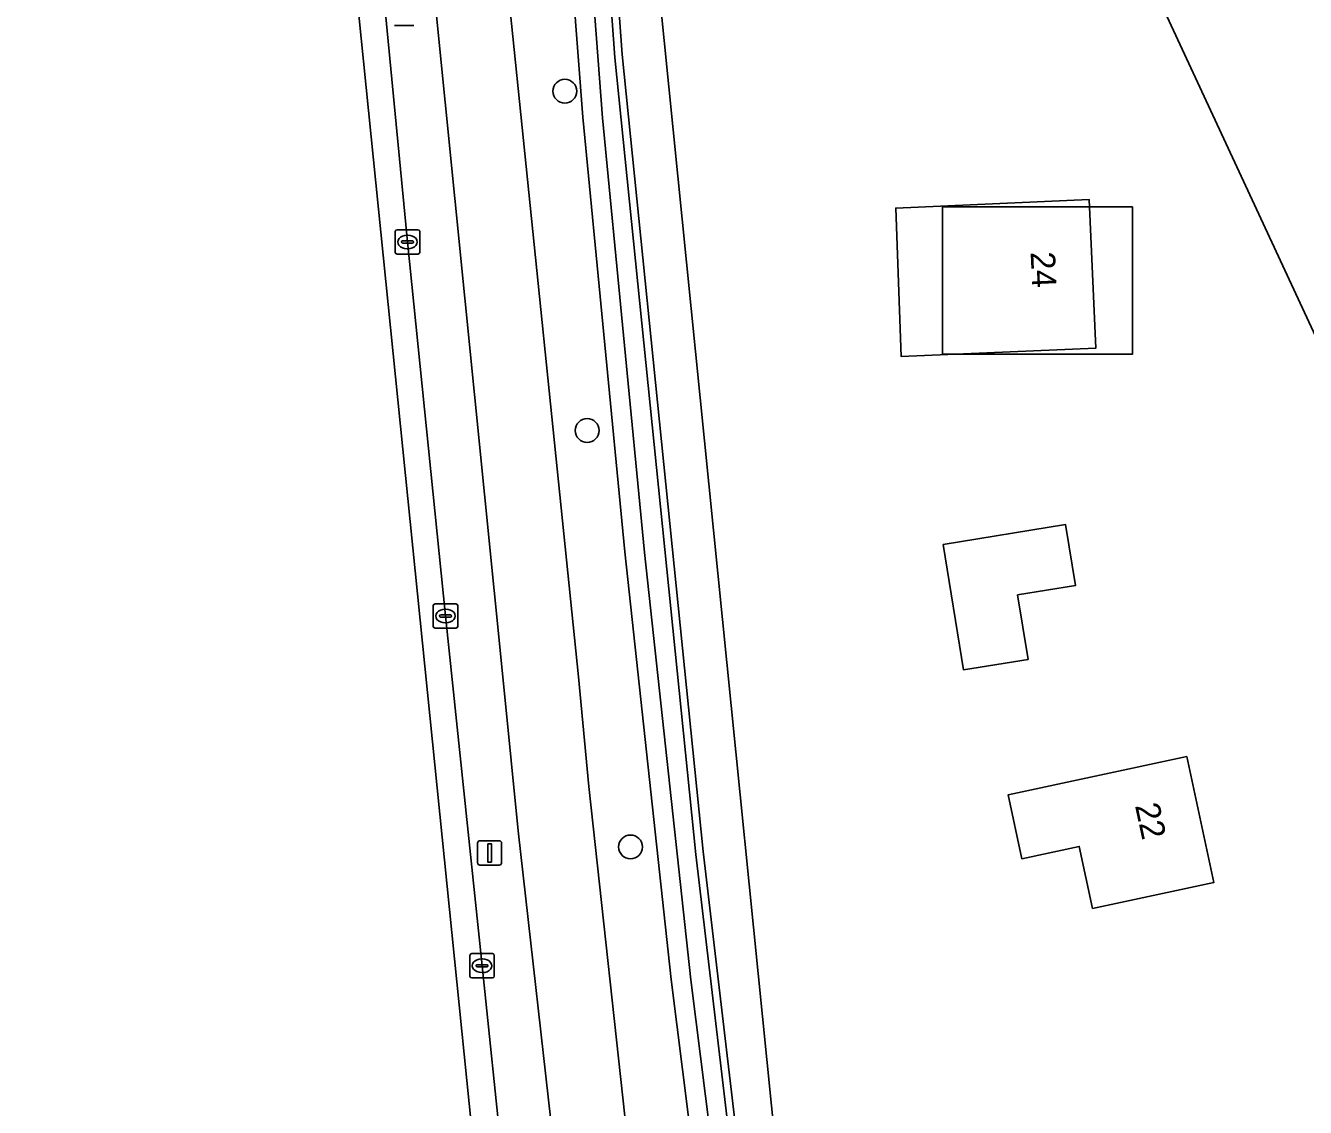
# Model space of a CAD drawing. Extents: x 159451 to 160664, y 388402 to 389723.
# Drawn here: x 159456.5 to 159509, y 389193.6 to 389238 of the extents above; entities that cross this region are included whole.
import ezdxf

# ---------------------------------------------------------------- set-up
doc = ezdxf.new("R2010")
doc.units = 0
for name, color, linetype in [('IMGEO_Berm_groen', 7, 'Continuous'), ('IMGEO_Boom', 7, 'Continuous'), ('IMGEO_Bouwland', 7, 'Continuous'), ('IMGEO_Fietspad_gesloten', 7, 'Continuous'), ('IMGEO_Greppel_droge_sloot', 7, 'Continuous'), ('IMGEO_Groenvoorziening', 7, 'Continuous'), ('IMGEO_Kolk', 7, 'Continuous'), ('IMGEO_Lichtmast', 7, 'Continuous'), ('IMGEO_Oever', 7, 'Continuous'), ('IMGEO_Pand', 7, 'Continuous'), ('IMGEO_Pand_nummerreeks', 7, 'Continuous'), ('IMGEO_Pand_vergunning_verleend', 7, 'Continuous'), ('IMGEO_Rijbaan_regionaal_gesloten', 7, 'Continuous')]:
    doc.layers.add(name, color=color, linetype=linetype)

msp = doc.modelspace()

# ---------------------------------------------------------------- linework, layer by layer
at = {"layer": 'IMGEO_Berm_groen'}
for points in [[(159479.81, 389178.066), (159478.244, 389191.231), (159476.688, 389204.954), (159476.115, 389210.723), (159473.293, 389238.955), (159471.683, 389255.143), (159470.151, 389272.51), (159468.609, 389291.384), (159467.063, 389310.472), (159465.649, 389329.916), (159464.342, 389348.5), (159462.508, 389376.402), (159461.071, 389403.687), (159459.294, 389436.93)], [(159459.237, 389397.341), (159460.45, 389376.955), (159461.584, 389357.574), (159462.193, 389348.076), (159462.91, 389337.218), (159464.392, 389316.843), (159466.081, 389296.525), (159467.728, 389277.179), (159468.669, 389266.005), (159469.405, 389257.836), (159470.673, 389244.477), (159472.153, 389229.121), (159473.713, 389213.767), (159475.213, 389199.409), (159476.055, 389191.357)]]:
    msp.add_lwpolyline(points, dxfattribs=at)
at = {"layer": 'IMGEO_Boom'}
for centre in [(159478.609, 389235.309), (159479.525, 389221.382), (159481.307, 389204.286)]:
    msp.add_circle(centre, 0.489, dxfattribs=at)
at = {"layer": 'IMGEO_Bouwland'}
for points in [[(159487.441, 389272.575), (159480.836, 389288.81), (159478.228, 389288.738), (159479.211, 389271.897), (159488.551, 389179.124), (159490.78, 389160.929), (159492.959, 389147.253), (159495.943, 389125.547), (159496.063, 389124.735), (159496.335, 389123.276), (159496.729, 389122.189), (159497.183, 389121.597), (159498.11, 389121.139), (159499.541, 389121.106), (159518.516, 389121.775), (159539.156, 389122.203), (159538.081, 389141.023), (159537.243, 389155.693), (159534.303, 389168.702), (159530.224, 389180.456)], [(159492.414, 389224.419), (159492.187, 389230.515), (159500.128, 389230.864), (159500.402, 389224.762)], [(159497.364, 389203.804), (159496.8, 389206.424), (159504.128, 389207.999), (159505.241, 389202.823), (159500.269, 389201.761), (159499.721, 389204.311)]]:
    msp.add_lwpolyline(points, close=True, dxfattribs=at)
at = {"layer": 'IMGEO_Fietspad_gesloten'}
for points in [[(159481.255, 389191.613), (159479.595, 389206.774), (159479.167, 389211.269), (159476.315, 389239.166), (159474.73, 389255.582), (159473.199, 389272.868), (159471.882, 389288.893), (159471.345, 389295.068), (159471.221, 389297.013), (159470.079, 389311.141), (159469.519, 389319.015), (159468.808, 389329.001), (159467.416, 389348.979), (159465.554, 389376.915), (159464.112, 389404.118)], [(159461.071, 389403.687), (159462.508, 389376.402), (159464.342, 389348.5), (159465.649, 389329.916), (159467.063, 389310.472), (159468.609, 389291.384), (159470.151, 389272.51), (159471.683, 389255.143), (159473.293, 389238.955), (159476.115, 389210.723), (159476.688, 389204.954), (159478.244, 389191.231), (159479.81, 389178.066)]]:
    msp.add_lwpolyline(points, dxfattribs=at)
at = {"layer": 'IMGEO_Greppel_droge_sloot'}
msp.add_lwpolyline([(159486.114, 389185.938), (159483.986, 389203.971), (159480.658, 389236.689), (159479.697, 389249.885), (159476.671, 389291.444), (159475.691, 389291.305), (159478.961, 389249.969), (159480.156, 389234.213), (159481.882, 389216.377), (159483.778, 389198.834), (159486.574, 389176.685)], dxfattribs=at)
at = {"layer": 'IMGEO_Groenvoorziening'}
for points in [[(159479.211, 389271.897), (159478.228, 389288.738), (159480.836, 389288.81), (159487.441, 389272.575), (159493.1, 389273.212), (159491.324, 389276.977), (159483.087, 389292.351), (159476.978, 389291.487), (159479.998, 389250), (159480.958, 389236.812), (159484.285, 389204.106), (159486.412, 389186.084)], [(159485.767, 389176.684), (159482.97, 389198.843), (159481.073, 389216.395), (159479.346, 389234.239), (159478.151, 389250), (159474.893, 389291.192), (159473.627, 389291.013)], [(159471.882, 389288.893), (159473.199, 389272.868), (159474.73, 389255.582), (159476.315, 389239.166), (159479.167, 389211.269), (159479.595, 389206.774), (159481.255, 389191.613), (159482.691, 389178.486), (159483.697, 389171.161), (159485.138, 389162.462), (159487.963, 389147.366), (159491.057, 389131.504), (159492.482, 389125.078), (159495.943, 389125.547), (159492.959, 389147.253), (159490.78, 389160.929), (159488.551, 389179.124), (159479.211, 389271.897)], [(159541.062, 389164.374), (159534.245, 389187.399), (159504.093, 389250), (159500, 389258.58), (159493.1, 389273.212), (159487.441, 389272.575), (159530.224, 389180.456), (159534.303, 389168.702), (159537.243, 389155.693), (159538.081, 389141.023), (159539.156, 389122.203), (159543.127, 389122.477), (159543.663, 389144.191)]]:
    msp.add_lwpolyline(points, dxfattribs=at)
at = {"layer": 'IMGEO_Kolk'}
for p, q in [((159471.652, 389228.695), (159471.652, 389229.547)), ((159471.727, 389229.621), (159472.579, 389229.621)), ((159471.911, 389229.115), (159471.911, 389229.127)), ((159471.954, 389229.164), (159472.352, 389229.164)), ((159472.14, 389229.401), (159472.165, 389229.401)), ((159472.395, 389229.127), (159472.395, 389229.115)), ((159472.653, 389229.547), (159472.653, 389228.695)), ((159472.579, 389228.621), (159471.727, 389228.621)), ((159472.349, 389229.078), (159471.951, 389229.078)), ((159472.163, 389228.841), (159472.138, 389228.841)), ((159473.212, 389213.341), (159473.212, 389214.193)), ((159473.287, 389214.267), (159474.139, 389214.267)), ((159473.7, 389214.047), (159473.725, 389214.047)), ((159474.213, 389214.193), (159474.213, 389213.341)), ((159473.471, 389213.761), (159473.471, 389213.773)), ((159473.909, 389213.724), (159473.511, 389213.724)), ((159473.514, 389213.81), (159473.912, 389213.81)), ((159473.723, 389213.487), (159473.698, 389213.487)), ((159473.955, 389213.773), (159473.955, 389213.761)), ((159474.139, 389213.267), (159473.287, 389213.267)), ((159474.712, 389198.983), (159474.712, 389199.835)), ((159474.787, 389199.909), (159475.639, 389199.909)), ((159475.713, 389199.835), (159475.713, 389198.983)), ((159474.971, 389199.403), (159474.971, 389199.415)), ((159475.409, 389199.366), (159475.011, 389199.366)), ((159475.014, 389199.452), (159475.412, 389199.452)), ((159475.2, 389199.689), (159475.225, 389199.689)), ((159475.455, 389199.415), (159475.455, 389199.403)), ((159475.639, 389198.909), (159474.787, 389198.909)), ((159475.223, 389199.129), (159475.198, 389199.129))]:
    msp.add_line(p, q, dxfattribs=at)
for points in [[(159471.652, 389228.695), (159471.652, 389229.547)], [(159471.727, 389229.621), (159472.579, 389229.621)], [(159472.653, 389229.547), (159472.653, 389228.695)], [(159472.579, 389228.621), (159471.727, 389228.621)], [(159473.212, 389213.341), (159473.212, 389214.193)], [(159473.287, 389214.267), (159474.139, 389214.267)], [(159474.213, 389214.193), (159474.213, 389213.341)], [(159474.139, 389213.267), (159473.287, 389213.267)], [(159474.712, 389198.983), (159474.712, 389199.835)], [(159474.787, 389199.909), (159475.639, 389199.909)], [(159475.713, 389199.835), (159475.713, 389198.983)], [(159475.639, 389198.909), (159474.787, 389198.909)]]:
    msp.add_lwpolyline(points, dxfattribs=at)
for centre, radius, start, end in [((159471.729, 389229.545), 0.0765, 91.552, 178.448), ((159471.729, 389229.545), 0.0765, 91.552, 178.448), ((159471.951, 389229.124), 0.0403, 85.8775, 175.7526), ((159471.948, 389229.114), 0.0366, 178.938, 274.7102), ((159472.352, 389229.121), 0.043, 264.8664, 352.4533), ((159472.356, 389229.126), 0.0386, 1.7309, 96.639), ((159472.577, 389229.545), 0.0765, 1.552, 88.448), ((159472.577, 389229.545), 0.0765, 1.552, 88.448), ((159471.729, 389228.697), 0.0765, 181.552, 268.448), ((159471.729, 389228.697), 0.0765, 181.552, 268.448), ((159472.577, 389228.697), 0.0765, 271.552, 358.448), ((159472.577, 389228.697), 0.0765, 271.552, 358.448), ((159473.289, 389214.191), 0.0765, 91.552, 178.448), ((159473.289, 389214.191), 0.0765, 91.552, 178.448), ((159474.137, 389214.191), 0.0765, 1.552, 88.448), ((159474.137, 389214.191), 0.0765, 1.552, 88.448), ((159473.511, 389213.77), 0.0403, 85.8775, 175.7526), ((159473.508, 389213.76), 0.0366, 178.938, 274.7102), ((159473.912, 389213.767), 0.043, 264.8664, 352.4533), ((159473.916, 389213.772), 0.0386, 1.7309, 96.639), ((159473.289, 389213.343), 0.0765, 181.552, 268.448), ((159473.289, 389213.343), 0.0765, 181.552, 268.448), ((159474.137, 389213.343), 0.0765, 271.552, 358.448), ((159474.137, 389213.343), 0.0765, 271.552, 358.448), ((159474.789, 389199.833), 0.0765, 91.552, 178.448), ((159474.789, 389199.833), 0.0765, 91.552, 178.448), ((159475.637, 389199.833), 0.0765, 1.552, 88.448), ((159475.637, 389199.833), 0.0765, 1.552, 88.448), ((159475.011, 389199.412), 0.0403, 85.8775, 175.7526), ((159475.008, 389199.402), 0.0366, 178.938, 274.7102), ((159475.412, 389199.409), 0.043, 264.8664, 352.4533), ((159475.416, 389199.414), 0.0386, 1.7309, 96.639), ((159474.789, 389198.985), 0.0765, 181.552, 268.448), ((159474.789, 389198.985), 0.0765, 181.552, 268.448), ((159475.637, 389198.985), 0.0765, 271.552, 358.448), ((159475.637, 389198.985), 0.0765, 271.552, 358.448)]:
    msp.add_arc(centre, radius, start, end, dxfattribs=at)
for centre, major_axis, ratio, start_param, end_param in [((159472.139, 389229.121), (-0.387, 0.002), 0.722429, 4.712389, 7.853982), ((159472.164, 389229.121), (-0.39, 0.002), 0.717154, 1.570796, 4.712389), ((159473.699, 389213.767), (-0.387, 0.002), 0.722429, 4.712389, 7.853982), ((159473.724, 389213.767), (-0.39, 0.002), 0.717154, 1.570796, 4.712389), ((159475.199, 389199.409), (-0.387, 0.002), 0.722429, 4.712389, 7.853982), ((159475.224, 389199.409), (-0.39, 0.002), 0.717154, 1.570796, 4.712389)]:
    msp.add_ellipse(centre, major_axis=major_axis, ratio=ratio, start_param=start_param, end_param=end_param, dxfattribs=at)
at = {"layer": 'IMGEO_Lichtmast'}
for p, q in [((159472.415, 389238.003), (159471.625, 389238.003)), ((159471.625, 389238.003), (159472.415, 389238.003)), ((159475.027, 389203.64), (159475.027, 389204.44)), ((159475.027, 389204.44), (159475.027, 389203.64)), ((159475.127, 389204.54), (159475.917, 389204.54)), ((159475.917, 389204.54), (159475.127, 389204.54)), ((159476.017, 389204.44), (159476.017, 389203.64)), ((159476.017, 389203.64), (159476.017, 389204.44)), ((159475.917, 389203.54), (159475.127, 389203.54)), ((159475.127, 389203.54), (159475.917, 389203.54))]:
    msp.add_line(p, q, dxfattribs=at)
msp.add_lwpolyline([(159475.447, 389204.415), (159475.597, 389204.415), (159475.597, 389203.665), (159475.447, 389203.665), (159475.447, 389204.415)], dxfattribs=at)
for centre, start, end in [((159475.127, 389204.44), 90, 180), ((159475.127, 389204.44), 90, 180), ((159475.917, 389204.44), 0, 90), ((159475.917, 389204.44), 360, 90), ((159475.127, 389203.64), 180, 270), ((159475.127, 389203.64), 180, 270), ((159475.917, 389203.64), 270, 0), ((159475.917, 389203.64), 270, 0)]:
    msp.add_arc(centre, 0.1, start, end, dxfattribs=at)
at = {"layer": 'IMGEO_Oever'}
for points in [[(159486.574, 389176.685), (159483.778, 389198.834), (159481.882, 389216.377), (159480.156, 389234.213), (159478.961, 389249.969), (159475.691, 389291.305), (159474.893, 389291.192), (159478.151, 389250), (159479.346, 389234.239), (159481.073, 389216.395), (159482.97, 389198.843), (159485.767, 389176.684)], [(159486.412, 389186.084), (159484.285, 389204.106), (159480.958, 389236.812), (159479.998, 389250), (159476.978, 389291.487), (159476.671, 389291.444), (159479.697, 389249.885), (159480.658, 389236.689), (159483.986, 389203.971), (159486.114, 389185.938)]]:
    msp.add_lwpolyline(points, dxfattribs=at)
at = {"layer": 'IMGEO_Pand'}
for points in [[(159500.128, 389230.864), (159492.187, 389230.515), (159492.414, 389224.419), (159500.402, 389224.762)], [(159504.128, 389207.999), (159496.8, 389206.424), (159497.364, 389203.804), (159499.721, 389204.311), (159500.269, 389201.761), (159505.241, 389202.823)]]:
    msp.add_lwpolyline(points, close=True, dxfattribs=at)
at = {"layer": 'IMGEO_Pand_vergunning_verleend'}
for points in [[(159494.105, 389224.51), (159494.105, 389230.558), (159501.904, 389230.558), (159501.904, 389224.51)], [(159494.132, 389216.702), (159499.161, 389217.522), (159499.569, 389215.022), (159497.187, 389214.633), (159497.619, 389211.986), (159494.971, 389211.554)]]:
    msp.add_lwpolyline(points, close=True, dxfattribs=at)
at = {"layer": 'IMGEO_Rijbaan_regionaal_gesloten'}
for points in [[(159456.481, 389421.006), (159461.772, 389332.122), (159463.341, 389305.754), (159468.546, 389254.372), (159476.395, 389176.888), (159474.251, 389152.87)], [(159476.055, 389191.357), (159475.213, 389199.409), (159473.713, 389213.767), (159472.153, 389229.121), (159470.673, 389244.477), (159469.405, 389257.836), (159468.669, 389266.005), (159467.728, 389277.179), (159466.081, 389296.525), (159464.392, 389316.843), (159462.91, 389337.218), (159462.193, 389348.076), (159461.584, 389357.574), (159460.45, 389376.955), (159459.237, 389397.341)]]:
    msp.add_lwpolyline(points, dxfattribs=at)

# ---------------------------------------------------------------- texts
at = {"layer": 'IMGEO_Pand_nummerreeks'}
for s, rotation, p in [('24', 272.5724, (159497.722, 389228.703)), ('22', 282.135, (159502.004, 389205.985))]:
    msp.add_text(s, height=1, rotation=rotation, dxfattribs=at).set_placement(p)

doc.saveas('drawing.dxf')
